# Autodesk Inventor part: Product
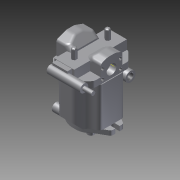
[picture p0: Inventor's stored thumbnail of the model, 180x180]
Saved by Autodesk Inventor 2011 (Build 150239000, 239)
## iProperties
Created: 2011-07
Part Number: Product
Document SubType Name: Modeling
Designer: khramov
Density: 1 g/cm^3
Mass: 3731.43 g
Surface Area: 1896.19 cm^2
Volume: 3731.43 cm^3
Стандарт преобразования: STEP AP203
Имя файла: VPPM-029.stp
Препроцессор: Mechanical Desktop 2011
Постпроцессор: Build: 239, Release: 2011 RTM - Date: Wed 02/17/2010
Отправленные единицы: миллиметр
Неопределенность: 1.0000000000000002e-06
Author: khramov
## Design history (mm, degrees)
feature "БазТело1"
sketch "Эскиз1"
  geometry: L1 (87, 0)-(-87, 0); L2 (0, 0)-(0, -107.805); L3 (-70, -7)-(-104.299, -7); L4 (-104.299, -7)-(-104.299, 7); L5 (-104.299, 7)-(-70, 7); L6 (70, -7)-(104.299, -7); L7 (104.299, 7)-(70, 7); L8 (104.299, -7)-(104.299, 7); A1 r 7 centre (-70, 0) between (-70, -7) and (-70, 7); A2 r 7 centre (70, 0) between (70, 7) and (70, -7)
  constraints: 16 end point, 5 symmetric about line, 4 point on circle, 2 centre point, 1 perpendicular, 1 tangent, 1 other
  dimensions: "d0" = 14 diameter of A1; "d1" = 70 distance from line of L2 A1.centre (derived)
extrude "Выдавливание1" cut sketch "Эскиз1" stored distance "d2" = 20; taper "d3" = 0 deg
sketch "Эскиз2"
  geometry: C1 r 50 at (0, 0); A1 r 60 centre (0, 0) between (-29.349, -52.332) and (29.349, -52.332) reference
  constraints: 1 centre point, 1 coincident
  dimensions: "d4" = 100 diameter of C1
extrude "Выдавливание2" join sketch "Эскиз2" distance "d5" = 10; taper "d6" = 0 deg
sketch "Эскиз3"
  geometry: C1 r 50 at (0, 0) reference; C2 r 11 at (0, 0)
  constraints: 1 centre point, 1 coincident
  dimensions: "d7" = 22 diameter of C2
extrude "Выдавливание3" join sketch "Эскиз3" distance "d8" = 36; taper "d9" = 0 deg
sketch "Эскиз4"
  geometry: C1 r 11 at (0, 0) reference; 1 further point
  constraints: 1 coincident
hole "Отверстие1" sketch "Эскиз4" at (0, 0) diameter "d10" = 4.917; stored, may be unused: countersink angle "d14" = 90 deg, drill point angle "d16" = 118 deg; dims "d11" = 6, "d12" = 7, "d13" = 2, "d15" = 8
chamfer "Фаска1" distance "d17" = 1.5; stored, may be unused: second distance "d18" = 2, angle "d19" = 45 deg
fillet "Сопряжение1" dims "d20" = 10
node "РабПлоскость1"
sketch "Эскиз5"
  geometry: L1 (0, -15.865)-(0, -45.332) reference; L2 (-10, -4)-(-10, 18) reference; L3 (-10, 7)-(332.11, 7); C1 r 13.75 at (37, -58); 1 further point
  constraints: 2 end point, 1 centre point, 1 midpoint, 1 perpendicular
  dimensions: "d22" = 27.5 diameter of C1; "d23" = 37 distance from line of C1.centre L1; "d24" = 65 distance from line of C1.centre L3
extrude "Выдавливание4" join sketch "Эскиз5" distance "d25" = 50; taper "d26" = 0 deg
sketch "Эскиз6"
  geometry: C1 r 13.75 at (0, 0) reference; 2 further points
  constraints: 1 coincident
hole "Отверстие2" sketch "Эскиз6" at (0, 0) diameter "d27" = 18.631; stored, may be unused: countersink angle "d31" = 90 deg, drill point angle "d33" = 118 deg; dims "d28" = 15, "d29" = 21, "d30" = 2, "d32" = 20
sketch "Эскиз7"
  geometry: L1 (-44.959, 9.458)-(-44.959, 4.541) reference; L2 (-44.959, 7)-(299.575, 7); L3 (0, -7.143)-(0, 0) reference; C1 r 16.5 at (110.5, 77); 1 further point
  constraints: 2 end point, 1 centre point, 1 midpoint, 1 perpendicular
  dimensions: "d34" = 33 diameter of C1; "d35" = 110.5 distance from line of L3 C1.centre; "d36" = 70 distance from line of C1.centre L2
extrude "Выдавливание5" join sketch "Эскиз7" distance "d37" = 60; taper "d38" = 0 deg
sketch "Эскиз8"
  geometry: C1 r 16.5 at (0, 0) reference; 2 further points
  constraints: 1 coincident
hole "Отверстие3" sketch "Эскиз8" at (0, 0) diameter "d39" = 18.631; stored, may be unused: countersink angle "d43" = 90 deg, drill point angle "d45" = 118 deg; dims "d40" = 15, "d41" = 21, "d42" = 2, "d44" = 20
fillet "Сопряжение2" dims "d46" = 5
sketch "Эскиз9"
  geometry: L1 (155, 51.91)-(155, 29.91) reference; L2 (191, 44.41)-(191, 37.41) reference; L3 (191, 40.91)-(-103.753, 40.91); L4 (145, 26.767)-(145, 33.91) reference; 2 further points
  constraints: 2 end point, 1 midpoint, 1 perpendicular, 1 point on line
  dimensions: "d47" = 170 distance from line of point (-25, 40.91) L4
hole "Отверстие4" sketch "Эскиз9" at (-25, 40.91) diameter "d48" = 32; stored, may be unused: countersink angle "d52" = 90 deg, drill point angle "d54" = 118 deg; dims "d49" = 15, "d50" = 21, "d51" = 2, "d53" = 20
sketch "Эскиз10"
  geometry: L1 (0, 96.41)-(0, 81.82) reference; L2 (-9.9, 11.56)-(-40.1, 11.56); L3 (-40.1, 11.56)-(-40.1, 70.26); L4 (-50, 5.41)-(-50, 76.41) reference; L5 (-40.1, 70.26)-(-9.9, 70.26); L6 (-9.9, 70.26)-(-9.9, 11.56); L7 (-25, 40.91)-(-25, 7.822); L8 (-25, 40.91)-(10.289, 40.91); C1 r 16 at (-25, 40.91) reference; 5 further points
  constraints: 12 end point, 4 coincident, 3 perpendicular, 2 parallel
  dimensions: "d55" = 30.2 distance of L2.start L2.end; "d56" = 58.7 distance of L5.end L2.start; "d57" = 15.1 distance between parallel lines of L7 L6; "d59" = 29.35 distance between parallel lines of L8 L2
hole "Отверстие5" sketch "Эскиз10" at (-9.9, 11.56), (-40.1, 11.56), (-40.1, 70.26), (-9.9, 70.26) diameter "d60" = 8.376; stored, may be unused: countersink angle "d64" = 90 deg, drill point angle "d66" = 118 deg; dims "d61" = 25, "d62" = 11, "d63" = 2, "d65" = 28
sketch "Эскиз11"
  geometry: L1 (77, 53.91)-(77, 27.91) reference; L2 (0, -16.59)-(0, 0) reference; L3 (77, 40.91)-(38, 40.91); L4 (-145, 33.91)-(-145, 26.767) reference; C1 r 9.5 at (38, 40.91); 1 further point
  constraints: 2 end point, 1 centre point, 1 coincident, 1 midpoint, 1 perpendicular
  dimensions: "d67" = 19 diameter of C1; "d68" = 183 distance from line of L4 C1.centre
extrude "Выдавливание6" cut sketch "Эскиз11" distance "d69" = 60; taper "d70" = 0 deg
sketch "Эскиз12"
  geometry: L1 (0, -16.59)-(0, 0) reference; L2 (49.9, 15.51)-(26.1, 15.51); L3 (26.1, 15.51)-(26.1, 66.31); L4 (26.1, 66.31)-(49.9, 66.31); L5 (49.9, 66.31)-(49.9, 15.51); L6 (55, -5.59)-(55, 87.41) reference; L7 (38, 40.91)-(38, 0); L8 (20, 5.41)-(57.311, 5.41) reference; L9 (38, 40.91)-(84.656, 40.91); C1 r 9.5 at (38, 40.91) reference; 5 further points
  constraints: 12 end point, 4 coincident, 3 parallel, 3 perpendicular
  dimensions: "d71" = 23.8 distance of L2.start L2.end; "d72" = 50.8 distance of L4.end L2.start; "d73" = 11.9 distance between parallel lines of L7 L5; "d74" = 25.4 distance between parallel lines of L9 L2
hole "Отверстие6" sketch "Эскиз12" at (49.9, 15.51), (26.1, 15.51), (26.1, 66.31), (49.9, 66.31) diameter "d75" = 8.376; stored, may be unused: countersink angle "d79" = 90 deg, drill point angle "d81" = 118 deg; dims "d76" = 20, "d77" = 11, "d78" = 2, "d80" = 24
sketch "Эскиз13"
  geometry: L1 (65, 0)-(0, 0) reference; L2 (65, 30)-(65, 0) reference; L3 (65, 30)-(0, 30); L4 (0, 30)-(0, 0); L5 (0, 0)-(65, 0); L6 (65, 0)-(65, 30); 1 further point
  constraints: 8 end point, 2 parallel, 1 horizontal, 1 perpendicular
extrude "Выдавливание7" join sketch "Эскиз13" distance "d82" = 2; taper "d83" = 0 deg
sketch "Эскиз14"
  geometry: L1 (5, 50)-(70, 50) reference; L2 (5, 20)-(5, 50) reference; L3 (12.5, 8)-(62.5, 8); L4 (62.5, 8)-(62.5, 49); L5 (62.5, 49)-(12.5, 49); L6 (12.5, 49)-(12.5, 8); 1 further point
  constraints: 8 end point, 2 parallel, 1 horizontal, 1 perpendicular
  dimensions: "d84" = 41 distance of L5.end L3.start; "d85" = 50 distance of L4.end L5.end; "d86" = 1 distance between parallel lines of L5 L1; "d87" = 65 distance of L1.start L1.end (derived); "d88" = 7.5 distance between parallel lines of L2 L6
extrude "Выдавливание8" join sketch "Эскиз14" distance "d89" = 15; taper "d90" = 0 deg
sketch "Эскиз15"
  geometry: L1 (194, -95.5)-(153, -95.5) reference; C1 r 13.5 at (173.5, -95.5); 1 further point
  constraints: 1 centre point, 1 midpoint
  dimensions: "d91" = 27 diameter of C1
extrude "Выдавливание9" join sketch "Эскиз15" distance "d92" = 30; taper "d94" = 0 deg; dims "d93" = 80, "d95" = 0
sketch "Эскиз16"
  geometry: C1 r 13.5 at (0, 0) reference; C2 r 6.5 at (0, 0); 1 further point
  constraints: 1 centre point, 1 coincident
  dimensions: "d96" = 13 diameter of C2
extrude "Выдавливание10" join sketch "Эскиз16" distance "d97" = 30; taper "d98" = 0 deg
sketch "Эскиз17"
  geometry: L1 (17.5, -132)-(17.5, -39) reference; L2 (0, -173)-(65, -173) reference; L3 (32.5, -173)-(32.5, 44.898); L4 (32.5, -148.733)-(25.5, -144.691); L5 (25.5, -144.691)-(25.5, -136.609); L6 (25.5, -136.609)-(32.5, -132.567); L7 (32.5, -132.567)-(39.5, -136.609); L8 (39.5, -136.609)-(39.5, -144.691); L9 (39.5, -144.691)-(32.5, -148.733); L10 (32.5, -38.433)-(25.5, -34.391); L11 (25.5, -34.391)-(25.5, -26.309); L12 (25.5, -26.309)-(32.5, -22.267); L13 (32.5, -22.267)-(39.5, -26.309); L14 (39.5, -26.309)-(39.5, -34.391); L15 (39.5, -34.391)-(32.5, -38.433); L16 (100, -69.5)-(100, -101.5) reference; L17 (100, -85.5)-(-95.927, -85.5); 3 further points
  constraints: 28 end point, 4 point on line, 2 midpoint, 1 parallel, 1 perpendicular, 26 other
  dimensions: "d99" = 14 distance between parallel lines of L8 L5; "d100" = 14 distance between parallel lines of L14 L11; "d101" = 110.3 distance of point (32.5, -30.35) point (32.5, -140.65); "d102" = 55.15 distance from line of L17 point (32.5, -140.65)
extrude "Выдавливание11" join sketch "Эскиз17" distance "d103" = 32; taper "d104" = 0 deg
fillet "Сопряжение3" dims "d105" = 5
fillet "Сопряжение4" dims "d106" = 30
fillet "Сопряжение5" dims "d107" = 15
fillet "Сопряжение6" dims "d108" = 30
fillet "Сопряжение7" dims "d109" = 10
fillet "Сопряжение8" dims "d110" = 15
node "5AB9"
other parameters: "d21" = -87
